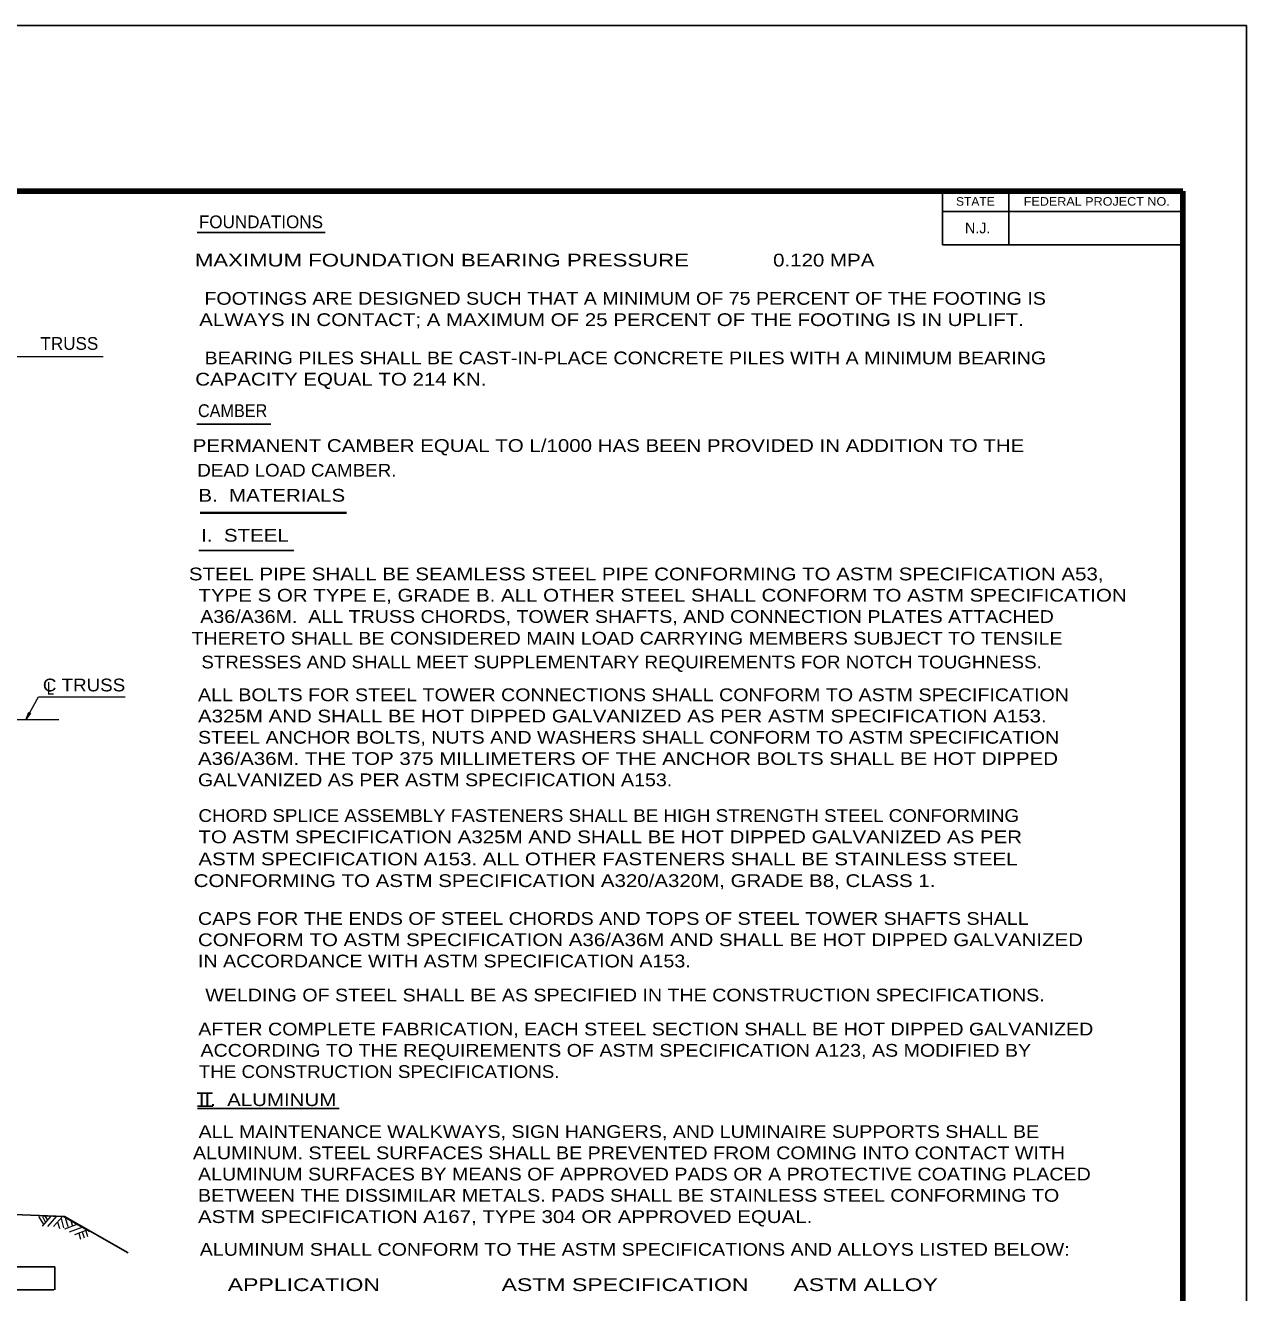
# Model space of a CAD drawing. Extents: x 312601.858 to 312602.699, y 144420.109 to 144420.704.
# Drawn here: x 312602.4116 to 312602.6988, y 144420.4055 to 144420.7035 of the extents above; entities that cross this region are included whole.
import ezdxf
from ezdxf.enums import TextEntityAlignment as Align

# ---------------------------------------------------------------- set-up
doc = ezdxf.new("R2010")
doc.units = 0
doc.header["$LTSCALE"] = 0.0012
doc.linetypes.add('DOT_DASHED', pattern=[7.7, 5, -1.2, 0.3, -1.2])
doc.linetypes.add('LONG_DASHED', pattern=[7.5, 6, -1.5])
for name, color, linetype, lineweight in [('1', 7, 'Continuous', 25), ('2', 7, 'Continuous', 13), ('39', 7, 'Continuous', 13), ('61', 7, 'Continuous', 25)]:
    doc.layers.add(name, color=color, linetype=linetype, lineweight=lineweight)

msp = doc.modelspace()

# ---------------------------------------------------------------- hatches: boundary and pattern name
at = {"layer": '39'}
msp.add_hatch(color=256, dxfattribs=at).paths.add_polyline_path([(312602.4126, 144420.5418), (312602.4128, 144420.5418), (312602.4118, 144420.5404), (312602.4124, 144420.542)])

# ---------------------------------------------------------------- linework, layer by layer
at = {"layer": '1', "linetype": 'DOT_DASHED', "lineweight": 13}
msp.add_line((312602.1761, 144420.5403), (312602.4195, 144420.5403), dxfattribs=at)
at = {"layer": '1'}
msp.add_line((312602.4208, 144420.4234), (312602.4358, 144420.4149), dxfattribs=at)
at = {"layer": '1', "linetype": 'LONG_DASHED'}
for p, q in [((312602.3885, 144420.4116), (312602.4185, 144420.4116)), ((312602.3885, 144420.4062), (312602.4183, 144420.4062))]:
    msp.add_line(p, q, dxfattribs=at)
at = {"layer": '1', "lineweight": 13}
msp.add_lwpolyline([(312602.4064, 144420.6256), (312602.4294, 144420.6256), (312602.4299, 144420.6256)], dxfattribs=at)
at = {"layer": '1'}
msp.add_lwpolyline([(312602.0446, 144420.4231), (312602.1024, 144420.4255), (312602.1292, 144420.4275), (312602.2324, 144420.4311), (312602.3359, 144420.4277), (312602.363, 144420.4257), (312602.4208, 144420.4234)], dxfattribs=at)
at = {"layer": '2', "lineweight": 25}
for p, q in [((312602.452, 144420.6548), (312602.4821, 144420.6548)), ((312602.4519, 144420.6097), (312602.4693, 144420.6097)), ((312602.4524, 144420.58), (312602.4747, 144420.58)), ((312602.452, 144420.4524), (312602.4556, 144420.4524)), ((312602.4521, 144420.4494), (312602.4557, 144420.4494)), ((312602.4521, 144420.4488), (312602.4854, 144420.4488)), ((312602.454, 144420.4494), (312602.4554, 144420.4494))]:
    msp.add_line(p, q, dxfattribs=at)
at = {"layer": '2', "lineweight": 35}
msp.add_line((312602.4527, 144420.5889), (312602.4871, 144420.5889), dxfattribs=at)
at = {"layer": '2'}
for p, q in [((312602.4147, 144420.4234), (312602.4158, 144420.4217)), ((312602.4156, 144420.4212), (312602.4177, 144420.4235)), ((312602.4156, 144420.4234), (312602.4163, 144420.4222)), ((312602.4163, 144420.4234), (312602.4168, 144420.4226)), ((312602.4169, 144420.4211), (312602.419, 144420.4235)), ((312602.4182, 144420.4211), (312602.4203, 144420.4234)), ((312602.4192, 144420.4222), (312602.4196, 144420.4206)), ((312602.42, 144420.423), (312602.4206, 144420.4208)), ((312602.421, 144420.4232), (312602.4216, 144420.4211)), ((312602.4223, 144420.4225), (312602.4226, 144420.4214)), ((312602.4209, 144420.4205), (312602.4238, 144420.4216)), ((312602.422, 144420.4198), (312602.425, 144420.4209)), ((312602.4232, 144420.4192), (312602.4261, 144420.4203)), ((312602.4242, 144420.4195), (312602.4246, 144420.4181)), ((312602.425, 144420.4198), (312602.4254, 144420.4184)), ((312602.4258, 144420.4201), (312602.4262, 144420.4187))]:
    msp.add_line(p, q, dxfattribs=at)
at = {"layer": '2', "linetype": 'LONG_DASHED', "lineweight": 25}
msp.add_line((312602.4185, 144420.4116), (312602.4185, 144420.4062), dxfattribs=at)
at = {"layer": '2'}
msp.add_lwpolyline([(312602.4118, 144420.5404), (312602.4147, 144420.5456), (312602.4351, 144420.5456)], dxfattribs=at)
at = {"layer": '2', "lineweight": 25}
msp.add_lwpolyline([(312602.4157, 144420.4236), (312602.4206, 144420.4234), (312602.4268, 144420.4199)], dxfattribs=at)
at = {"layer": '39', "lineweight": 25}
for p, q in [((312601.8578, 144420.7035), (312602.6988, 144420.7035)), ((312602.6988, 144420.1095), (312602.6988, 144420.7035)), ((312602.5735, 144420.6645), (312602.6838, 144420.6645))]:
    msp.add_line(p, q, dxfattribs=at)
at = {"layer": '39', "lineweight": 158}
for p in [(312601.9088, 144420.6645), (312602.6838, 144420.1247)]:
    msp.add_line(p, (312602.6838, 144420.6645), dxfattribs=at)
at = {"layer": '39'}
msp.add_lwpolyline([(312602.4126, 144420.5418), (312602.4128, 144420.5418), (312602.4118, 144420.5404), (312602.4124, 144420.542)], close=True, dxfattribs=at)
at = {"layer": '61'}
for p, q in [((312602.6273, 144420.6645), (312602.6273, 144420.6519)), ((312602.6429, 144420.6645), (312602.6429, 144420.6519)), ((312602.6838, 144420.6597), (312602.6273, 144420.6597)), ((312602.6838, 144420.6519), (312602.6273, 144420.6519))]:
    msp.add_line(p, q, dxfattribs=at)

# ---------------------------------------------------------------- texts
at = {"layer": '2'}
for s, p in [('FOUNDATIONS', (312602.467, 144420.6558)), ('TRUSS', (312602.42195, 144420.6272))]:
    msp.add_text(s, height=0.003, dxfattribs=at).set_placement(p, align=Align.CENTER)
for s, width, p in [('MAXIMUM FOUNDATION BEARING PRESSURE              ', 1.3, (312602.5197, 144420.6468)), ('0.120 MPA', 1.2, (312602.59935, 144420.6468)), ('FOOTINGS ARE DESIGNED SUCH THAT A MINIMUM OF 75 PERCENT OF THE FOOTING IS', 1.15, (312602.55265, 144420.6378)), ('ALWAYS IN CONTACT; A MAXIMUM OF 25 PERCENT OF THE FOOTING IS IN UPLIFT.', 1.2, (312602.54945, 144420.6328)), ('BEARING PILES SHALL BE CAST-IN-PLACE CONCRETE PILES WITH A MINIMUM BEARING', 1.15, (312602.5527, 144420.6238)), ('CAPACITY EQUAL TO 214 KN.', 1.2, (312602.4858, 144420.6188)), ('CAMBER', 0.95, (312602.46035, 144420.6114)), ('PERMANENT CAMBER EQUAL TO L/1000 HAS BEEN PROVIDED IN ADDITION TO THE ', 1.2, (312602.5494, 144420.6032)), ('DEAD LOAD CAMBER.', 1.1, (312602.47545, 144420.5974)), ('B.  MATERIALS', 1.2, (312602.46955, 144420.5915)), ('I.  STEEL', 1.2, (312602.46325, 144420.5821)), ('STEEL PIPE SHALL BE SEAMLESS STEEL PIPE CONFORMING TO ASTM SPECIFICATION A53,', 1.2, (312602.5576, 144420.573)), ('A36/A36M.  ALL TRUSS CHORDS, TOWER SHAFTS, AND CONNECTION PLATES ATTACHED', 1.15, (312602.5531, 144420.563)), ('THERETO SHALL BE CONSIDERED MAIN LOAD CARRYING MEMBERS SUBJECT TO TENSILE', 1.15, (312602.5531, 144420.5579)), ('STRESSES AND SHALL MEET SUPPLEMENTARY REQUIREMENTS FOR NOTCH TOUGHNESS.', 1.1, (312602.5518, 144420.5523)), ('C TRUSS', 1.1, (312602.4254, 144420.5469)), ('L', 0.75, (312602.41755, 144420.5461)), ('CONFORMING TO ASTM SPECIFICATION A320/A320M, GRADE B8, CLASS 1.', 1.2, (312602.5384, 144420.5009)), ('WELDING OF STEEL SHALL BE AS SPECIFIED IN THE CONSTRUCTION SPECIFICATIONS. ', 1.15, (312602.55325, 144420.474)), ('AFTER COMPLETE FABRICATION, EACH STEEL SECTION SHALL BE HOT DIPPED GALVANIZED', 1.15, (312602.5575, 144420.466)), ('ACCORDING TO THE REQUIREMENTS OF ASTM SPECIFICATION A123, AS MODIFIED BY', 1.15, (312602.55045, 144420.461)), ('THE CONSTRUCTION SPECIFICATIONS.', 1.1, (312602.4948, 144420.456)), ('II.  ALUMINUM', 1.2, (312602.46855, 144420.4494)), ('ALL MAINTENANCE WALKWAYS, SIGN HANGERS, AND LUMINAIRE SUPPORTS SHALL BE  ', 1.15, (312602.55245, 144420.4419)), ('ALUMINUM. STEEL SURFACES SHALL BE PREVENTED FROM COMING INTO CONTACT WITH', 1.15, (312602.55355, 144420.4369)), ('ALUMINUM SHALL CONFORM TO THE ASTM SPECIFICATIONS AND ALLOYS LISTED BELOW:', 1.15, (312602.5549, 144420.4142)), ('APPLICATION                   ASTM SPECIFICATION       ASTM ALLOY', 1.35, (312602.5427, 144420.4059))]:
    msp.add_text(s, height=0.003, dxfattribs=dict(at, width=width)).set_placement(p, align=Align.CENTER)
for s, width, p in [('TYPE S OR TYPE E, GRADE B. ALL OTHER STEEL SHALL CONFORM TO ASTM SPECIFICATION', 1.2, (312602.4523, 144420.568)), ('ALL BOLTS FOR STEEL TOWER CONNECTIONS SHALL CONFORM TO ASTM SPECIFICATION', 1.15, (312602.4522, 144420.5446)), ('A325M AND SHALL BE HOT DIPPED GALVANIZED AS PER ASTM SPECIFICATION A153. ', 1.2, (312602.4522, 144420.5396)), ('STEEL ANCHOR BOLTS, NUTS AND WASHERS SHALL CONFORM TO ASTM SPECIFICATION', 1.15, (312602.4522, 144420.5346)), ('A36/A36M. THE TOP 375 MILLIMETERS OF THE ANCHOR BOLTS SHALL BE HOT DIPPED', 1.2, (312602.4522, 144420.5296)), ('GALVANIZED AS PER ASTM SPECIFICATION A153.', 1.15, (312602.4522, 144420.5246)), ('CHORD SPLICE ASSEMBLY FASTENERS SHALL BE HIGH STRENGTH STEEL CONFORMING', 1.1, (312602.4523, 144420.5162)), ('TO ASTM SPECIFICATION A325M AND SHALL BE HOT DIPPED GALVANIZED AS PER', 1.2, (312602.4523, 144420.5112)), ('ASTM SPECIFICATION A153. ALL OTHER FASTENERS SHALL BE STAINLESS STEEL', 1.2, (312602.4523, 144420.506)), ('CAPS FOR THE ENDS OF STEEL CHORDS AND TOPS OF STEEL TOWER SHAFTS SHALL', 1.15, (312602.4522, 144420.492)), ('CONFORM TO ASTM SPECIFICATION A36/A36M AND SHALL BE HOT DIPPED GALVANIZED', 1.2, (312602.4522, 144420.487)), ('IN ACCORDANCE WITH ASTM SPECIFICATION A153.', 1.15, (312602.4522, 144420.482)), ('ALUMINUM SURFACES BY MEANS OF APPROVED PADS OR A PROTECTIVE COATING PLACED', 1.15, (312602.4522, 144420.4319)), ('BETWEEN THE DISSIMILAR METALS. PADS SHALL BE STAINLESS STEEL CONFORMING TO', 1.15, (312602.4522, 144420.4269)), ('ASTM SPECIFICATION A167, TYPE 304 OR APPROVED EQUAL.', 1.2, (312602.4522, 144420.4219))]:
    msp.add_text(s, height=0.003, dxfattribs=dict(at, width=width)).set_placement(p)
at = {"layer": '61'}
for s, width, p in [('STATE', 1.05, (312602.635, 144420.6611)), ('FEDERAL PROJECT NO.', 1.1, (312602.66355, 144420.6611))]:
    msp.add_text(s, height=0.00201, dxfattribs=dict(at, width=width)).set_placement(p, align=Align.CENTER)
msp.add_text('N.J.', height=0.002512, dxfattribs=at).set_placement((312602.63555, 144420.6546), align=Align.CENTER)

doc.saveas('drawing.dxf')
